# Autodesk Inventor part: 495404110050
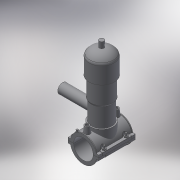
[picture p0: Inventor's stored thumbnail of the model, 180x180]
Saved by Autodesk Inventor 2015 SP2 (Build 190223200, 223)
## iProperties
Created: 2017-07
Part Number: 495404110050
Material: Generic
Description: PLASSON TAPPING VALVE 110-50
Document SubType Name: Modeling
Designer: KIM
Density: 1 g/cm^3
Appearance: Default
Author: KIM
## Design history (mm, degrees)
derived "495404-4954S4.ipt"
feature "Solid1::495404-4954S4.ipt"
feature "Solid2::495404-4954S4.ipt"
tag "TaggingFeature1"
body "Solid1"
body "Solid2"
other parameters: "d2" = 148, "d3" = 27.5, "d4" = 118, "d5" = 0, "d6" = 0.1, "d8" = 0, "d19" = 6, "d20" = 6, "d21" = 70.8, "d23" = 0, "d24" = 35.4, "d26" = 0, "d27" = 3, "d28" = 3, "d29" = 3, "d30" = 36.66667, "d31" = 6, "d32" = 0, "d33" = 0, "d34" = 0.6, "d40" = 71.5, "d47" = 119.75, "d70" = 15, "d72" = 0, "d73" = 6, "d75" = 5, "d76" = 0, "d77" = 5.5, "d78" = 85, "d79" = 15, "d80" = 47.2, "d82" = 5 deg, "d84" = 4, "d85" = 14, "d86" = 0, "d87" = 3, "d88" = 0, "d89" = 1, "d90" = 1, "d91" = 94.4, "d92" = 0, "d93" = 0.5, "d94" = 57.89474, "d96" = 141.625, "d97" = 2.36, "d98" = 0, "d120" = 140 deg, "d121" = 24.228, "d122" = 20 deg, "d123" = 275, "d124" = 82.5, "d126" = 0, "d143" = 113.3, "d145" = 21.15385, "d149" = 1.65, "d150" = 23.26923, "d153" = 118, "d154" = 0, "d156" = 68.75, "d157" = 160 deg, "d159" = 5.5, "d161" = 1.65, "d162" = 70.8, "d163" = 0, "d164" = 55, "d167" = 11, "d168" = 67.07317, "d170" = 3, "d172" = 0, "d173" = 1, "d175" = 55, "d176" = 20 deg, "d177" = 7.7, "d178" = 27.5, "d180" = 0, "d183" = 11, "d184" = 6.16, "d185" = 38.35, "d186" = 38.35, "d187" = 68.75, "d188" = 8.25, "d189" = 7.7, "d190" = 0, "d191" = 103.125, "d193" = 6.8, "d194" = 2.95, "d195" = 90 deg, "d197" = 0, "d199" = 0, "d205" = 14.64, "d206" = 81.33333, "d207" = 244, "d208" = 224.48, "d209" = 207.4, "d210" = 200.08, "d211" = 146.4, "d212" = 85.4, "d213" = 65.88, "d214" = 73.2, "d216" = 19.52, "d217" = 70.76, "d218" = 80.52, "d222" = 0, "d223" = 137.5, "d224" = 152, "d225" = 51, "d229" = 152, "d230" = 0, "B_" = 148, "H_" = 152, "L_" = 118, "d_t" = 6, "H_1" = 51, "H_2" = 244, "d148" = 1.65, "d160" = 1.65, "d169" = 3, "d192" = 6.8
